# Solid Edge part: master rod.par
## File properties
Author: Administrator
Template: normal.par
Last saved by: CADCIM
Revision: 10
Application: Solid Edge
Accuracy: 0.99
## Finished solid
Body 1: solid body, 60 faces, 148 edges, 80 vertices.
  Faces by surface: cylinder 42, plane 18
  Edges by curve: circle 78, line 58, ellipse 12
Bounding box of the edges (mm): 320.500 x 112.000 x 70.000, from (-118.4884, -56, -35) to (202.0116, 56, 35).
Cylindrical faces by radius (mm): R5 x8, R6 x4, R12 x1, R13 x8, R17.5 x1, R26 x1, R31.5 x3, R35 x2, R72.03 x8, R78 x4, R207.0766 x1, R207.2725 x1
Planar faces by outward normal: +y 2, +z 5, -y 2, -z 5, oblique 4
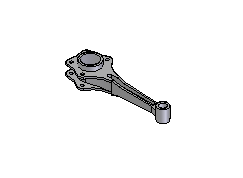
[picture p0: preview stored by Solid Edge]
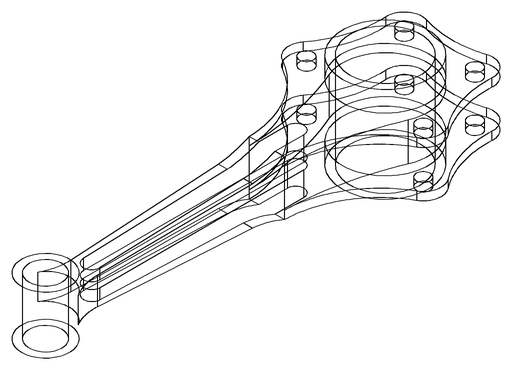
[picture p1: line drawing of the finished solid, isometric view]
